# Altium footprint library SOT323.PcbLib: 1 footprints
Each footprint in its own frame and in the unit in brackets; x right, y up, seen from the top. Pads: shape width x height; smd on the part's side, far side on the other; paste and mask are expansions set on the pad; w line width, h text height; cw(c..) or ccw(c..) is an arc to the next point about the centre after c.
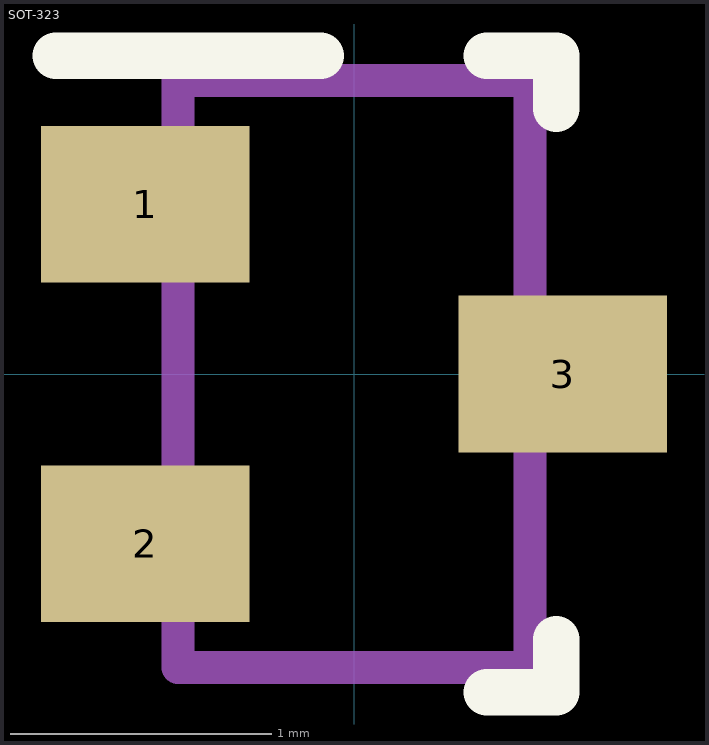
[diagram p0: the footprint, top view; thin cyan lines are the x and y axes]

## SOT-323 [mm] "Zetex recommended land pattern.  March 2007"
height 1.1
pads (3):
  rect 0.8x0.6 smd: 1(-0.8,0.65) 2(-0.8,-0.65) 3(0.8,0)
Top Overlay:
  lines w0.178: -1.143,1.219 -0.127,1.219 ; 0.508,-1.219 0.775,-1.219 0.775,-1.016 ; 0.508,1.219 0.775,1.219 0.775,1.016
M5 Assembly Top:
  lines w0.127: -1.125,-0.8 -0.975,-0.8 -0.935,-0.8 -0.884,-0.8 -0.725,-0.8 -0.675,-0.8 -0.675,-0.5 -0.725,-0.5 -0.884,-0.5 -0.935,-0.5 -0.975,-0.5 -1.125,-0.5 -1.125,-0.8 ; -1.125,0.5 -0.975,0.5 -0.935,0.5 -0.884,0.5 -0.725,0.5 -0.675,0.5 -0.675,0.8 -0.725,0.8 -0.884,0.8 -0.935,0.8 -0.975,0.8 -1.125,0.8 -1.125,0.5 ; -0.675,-1.125 0.675,-1.125 0.675,1.125 -0.675,1.125 -0.675,-1.125 ; 0.675,-0.15 0.675,0.15 0.725,0.15 0.884,0.15 0.935,0.15 0.975,0.15 1.125,0.15 1.125,-0.15 0.975,-0.15 0.935,-0.15 0.884,-0.15 0.725,-0.15 0.675,-0.15
  text ".Designator" at -0.25,0.925 h0.51
3D body: height 1.13, standoff 0.02, extent -1.125,-1.125 1.125,1.125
